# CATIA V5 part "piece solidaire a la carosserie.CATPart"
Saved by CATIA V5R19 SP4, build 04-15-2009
Part number: element accroché à la carosserie
Bounding box of the stored display mesh (mm): x -13.29 to 168.34, y -68.5 to 68.5, z 0 to 150.895
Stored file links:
  G:\EU_thinkMotion\CFAO_2010\MMS_groupe1\MMS_groupe1\A reprendre\OK\rdeneffle\piece solidaire a la carosserie.CATPart
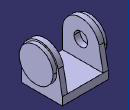
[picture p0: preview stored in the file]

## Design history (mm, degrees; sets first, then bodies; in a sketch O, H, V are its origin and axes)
Parameters
  `rayon support carosserie` = 62 mm
Body1 (main body)
  Sketch1 on yz-plane, origin (0, 0, 0), H (0, 1, 0), V (0, 0, 1)
    line L1 (-68.5, 0) -> (68.5, 0)
    line L2 (68.5, 0) -> (68.5, 27)
    point P3 (68.5, 27)
    line L3 (68.5, 27) -> (54.3906, 100.5801)
    point P4 (68.5, 27)
    point P5 (54.3906, 100.5801)
    arc A1 centre (-6.5, 88.904) radius 62 from (-68.5, 88.904) to (54.3906, 100.5801) cw
    point P8 (54.3906, 100.5801)
    line L4 (-68.5, 0) -> (-68.5, 88.904)
    point P9 (-68.5, 88.904)
    length L1 = 137
    length L2 = 27
    length L3 = 74.9206
    radius A1 = 62 {= `rayon support carosserie`}
    horizontal: L1 H
    vertical: L2 V
    coincidence: P4 L2, A1 P5, P3 P4, P5 P8, P9 A1
    tangency: A1 L3, L4 A1
  Pad1: profile Sketch1, direction (1, 0, 0), length 155.05
  Sketch2 on start face of Pad1, origin (0, 0, 0), H (0, -1, 0), V (0, 0, 1)
    circle A1 centre (6.5, 88.904) radius 57
    reference projected arc E1 centre (6.5, 88.904) radius 62 from (68.5, 88.904) to (-54.3906, 100.5801) ccw from edge [start face of Pad1 | face of Pad1 from Sketch1.A1]
    radius A1 = 57
    concentricity: A1 E1
  Pad2: profile Sketch2, direction (-1, 0, 0), length 13.29
  Sketch3 on end face of Pad1, origin (155.05, 0, 0), H (0, 1, 0), V (0, 0, 1)
    circle A1 centre (-6.5, 88.904) radius 57
    reference projected arc E1 centre (-6.5, 88.904) radius 62 from (54.3906, 100.5801) to (-68.5, 88.904) ccw from edge [face of Pad1 from Sketch1.A1 | end face of Pad1]
    radius A1 = 57
    concentricity: A1 E1
  Pad3: profile Sketch3, direction (1, 0, 0), length 13.29
  Point1: (0, -6.5, 151.892)
  Plane1: type Tangent, Support face of Pad2, RefPoint Point1
  Sketch4 on Plane1, origin (0, 15.652, 151.892), H (1, 0, 0), V (0, -1, 0)
    line L1 (17.72, 84.152) -> (137.33, 84.152)
    line L2 (137.33, 84.152) -> (137.33, -52.848)
    line L3 (137.33, -52.848) -> (17.72, -52.848)
    line L4 (17.72, -52.848) -> (17.72, 84.152)
    reference projected line E1 (0, 84.152) -> (155.05, 84.152) from edge [face of Pad1 from Sketch1.L4 | face of Pad2]
    reference projected line E2 (0, -52.848) -> (155.05, -52.848) from edge [face of Pad1 from Sketch1.L2 | face of Pad1 from Sketch1.L1]
    reference projected line E3 (155.05, 68.1382) -> (155.05, -68.1382) from edge [face of Pad1 from Sketch1.L1 | end face of Pad1]
    reference projected line E4 (0, 68.1382) -> (0, -68.1382) from edge [start face of Pad1 | face of Pad1 from Sketch1.L1]
    distance L1 E1 = 0
    distance L3 E2 = 0
    distance L2 E3 = 17.72
    distance L4 E4 = 17.72
    horizontal: L1 H, L3 H
    vertical: L2 V, L4 V
  Pocket1: profile Sketch4, direction (0, 0, -1), length 124.892
  Sketch5 on face of Pocket1 from Sketch4.L2, origin (137.33, 0, 0), H (0, -1, 0), V (0, 0, 1)
    circle A1 centre (6.5, 88.904) radius 23
    reference projected circle E1 centre (6.5, 88.904) radius 57 from edge [face of Pad2 from Sketch2.A1 | end face of Pad2]
    radius A1 = 23
    concentricity: A1 E1
  Pocket2: profile Sketch5, direction (1, 0, 0), length 28
  Sketch6 on face of Pocket1 from Sketch4.L4, origin (17.72, 0, 0), H (0, 1, 0), V (0, 0, 1)
    circle A1 centre (-6.5, 88.904) radius 23
    reference projected arc E1 centre (-6.5, 88.904) radius 62 from (54.3906, 100.5801) to (-68.5, 88.904) ccw from edge [face of Pad1 from Sketch1.A1 | end face of Pad1]
    radius A1 = 23
    concentricity: A1 E1
  Pocket3: profile Sketch6, direction (-1, 0, 0), length 28
  Plane2: type Offset, RefPlane face of Pocket1 from Sketch4.L4, Offset 20
  Sketch7 on Plane2, origin (-2.28, 0, 0), H (0, -1, 0), V (0, 0, 1)
    circle A1 centre (6.5, 88.904) radius 40
    reference projected arc E1 centre (6.5, 88.904) radius 62 from (68.5, 88.904) to (-54.3906, 100.5801) ccw from edge [start face of Pad1 | face of Pad1 from Sketch1.A1]
    radius A1 = 40
    concentricity: A1 E1
  Pocket4: profile Sketch7, direction (-1, 0, 0), length 8
  Plane3: type Offset, RefPlane face of Pocket1 from Sketch4.L2, Offset 20
  Sketch8 on Plane3, origin (157.33, 0, 0), H (0, 1, 0), V (0, 0, 1)
    circle A1 centre (-6.5, 88.904) radius 40
    reference projected arc E1 centre (-6.5, 88.904) radius 62 from (54.3906, 100.5801) to (-68.5, 88.904) ccw from edge [face of Pad1 from Sketch1.A1 | end face of Pad1]
    radius A1 = 40
    concentricity: A1 E1
  Pocket5: profile Sketch8, direction (1, 0, 0), length 8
